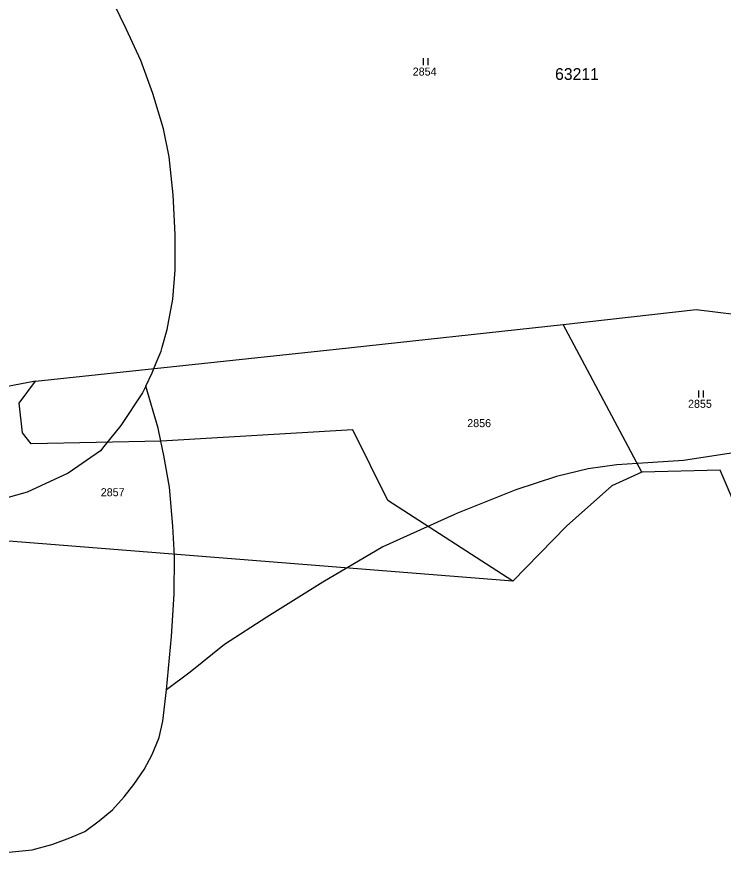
# Model space of a CAD drawing. Extents: x -546762 to -540209, y -1046851 to -1035694.
# Drawn here: x -542696.6 to -542546.6, y -1038616.7 to -1038439.2 of the extents above; entities that cross this region are included whole.
import ezdxf

# ---------------------------------------------------------------- set-up
doc = ezdxf.new("R2010")
doc.units = 0
for name, color, linetype in [('Vrstva 1', 7, 'Continuous'), ('Vrstva 18', 7, 'Continuous'), ('Vrstva 25', 7, 'Continuous'), ('Vrstva 52', 7, 'Continuous'), ('Vrstva 53', 7, 'Continuous')]:
    doc.layers.add(name, color=color, linetype=linetype)

msp = doc.modelspace()

# ---------------------------------------------------------------- linework, layer by layer
at = {"layer": 'Vrstva 1'}
for points in [[(-542580.56, -1038504.59), (-542552.33, -1038501.39)], [(-542552.33, -1038501.39), (-542539.61, -1038502.93)], [(-542628.8, -1038509.81), (-542580.56, -1038504.59)], [(-542563.89, -1038535.91), (-542580.56, -1038504.59)], [(-542692.62, -1038516.57), (-542628.8, -1038509.81)], [(-542692.62, -1038516.57), (-542747.19, -1038527.04)], [(-542696.09, -1038521.29), (-542692.62, -1038516.57)], [(-542695.43, -1038527.56), (-542696.09, -1038521.29)], [(-542693.58, -1038529.95), (-542695.43, -1038527.56)], [(-542625.27, -1038526.91), (-542665.94, -1038529.38)], [(-542617.78, -1038541.95), (-542625.27, -1038526.91)], [(-542665.94, -1038529.38), (-542693.58, -1038529.95)], [(-542563.89, -1038535.91), (-542570.26, -1038538.82)], [(-542547.19, -1038535.52), (-542563.89, -1038535.91)], [(-542536.47, -1038560.68), (-542547.19, -1038535.52)], [(-542570.26, -1038538.82), (-542579.83, -1038547.38)], [(-542591.23, -1038559.12), (-542617.78, -1038541.95)], [(-542591.23, -1038559.12), (-542735.84, -1038547.59)], [(-542579.83, -1038547.38), (-542591.23, -1038559.12)]]:
    msp.add_lwpolyline(points, dxfattribs=at)
at = {"layer": 'Vrstva 25'}
for p, q in [((-542610.22, -1038449.46), (-542610.22, -1038447.96)), ((-542609.22, -1038449.46), (-542609.22, -1038447.96)), ((-542551.74, -1038520.05), (-542551.74, -1038518.55)), ((-542550.74, -1038520.05), (-542550.74, -1038518.55))]:
    msp.add_line(p, q, dxfattribs=at)
at = {"layer": 'Vrstva 52'}
for points in [[(-542669.21, -1038517.65), (-542667.85, -1038514.81), (-542666.99, -1038512.7), (-542665.97, -1038510.2), (-542665.73, -1038509.35), (-542664.69, -1038505.59), (-542663.49, -1038499.19), (-542662.98, -1038493.04), (-542662.98, -1038485.44), (-542663.39, -1038477.02), (-542664.28, -1038468.95), (-542665.48, -1038462.98), (-542667.72, -1038455.5), (-542670.26, -1038448.48), (-542673.39, -1038441.75), (-542677.13, -1038433.98), (-542687.72, -1038415.16)], [(-542669.21, -1038517.65), (-542669.9, -1038519.08), (-542674.51, -1038526), (-542678.1, -1038530.45), (-542678.85, -1038531.38), (-542685.72, -1038536.16), (-542694.38, -1038540.2), (-542703.04, -1038542.59), (-542712.45, -1038543.34)], [(-542664.21, -1038539.15), (-542665.41, -1038532.4), (-542666.04, -1038529.34), (-542666.6, -1038526.6), (-542669.21, -1038517.65)], [(-542543.49, -1038531.67), (-542554.99, -1038533.47), (-542564.77, -1038534.08), (-542569.18, -1038534.36), (-542575.27, -1038535.22), (-542581.99, -1038536.87), (-542590.65, -1038539.7), (-542602.99, -1038544.67), (-542603.65, -1038544.94), (-542618.88, -1038551.81), (-542631.58, -1038559.28), (-542643.53, -1038566.76), (-542652.49, -1038572.58), (-542659.81, -1038578.41)], [(-542664.81, -1038582.15), (-542663.79, -1038570.83), (-542663.19, -1038561.87), (-542663.1, -1038553.75), (-542663.45, -1038547.43), (-542664.21, -1038539.15)], [(-542659.81, -1038578.41), (-542664.81, -1038582.15)], [(-542698.32, -1038616.7), (-542693.37, -1038616.19), (-542689.19, -1038615.08), (-542688.94, -1038614.99), (-542685.34, -1038613.63), (-542682.19, -1038612.26), (-542679.11, -1038610.04), (-542676.3, -1038607.65), (-542673.82, -1038604.92), (-542671.77, -1038602.27), (-542669.55, -1038599.11), (-542667.85, -1038595.95), (-542666.4, -1038592.28), (-542665.63, -1038588.86), (-542664.81, -1038582.15)]]:
    msp.add_lwpolyline(points, dxfattribs=at)

# ---------------------------------------------------------------- texts
at = {"layer": 'Vrstva 18'}
for s, p in [('2854', (-542612.52, -1038451.67)), ('2855', (-542554.04, -1038522.26)), ('2856', (-542600.94, -1038526.37)), ('2857', (-542678.78, -1038541.05))]:
    msp.add_text(s, height=1.7, dxfattribs=at).set_placement(p)
at = {"layer": 'Vrstva 53'}
msp.add_text('63211', height=2.5, dxfattribs=at).set_placement((-542582.28, -1038452.59))

doc.saveas('drawing.dxf')
